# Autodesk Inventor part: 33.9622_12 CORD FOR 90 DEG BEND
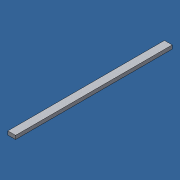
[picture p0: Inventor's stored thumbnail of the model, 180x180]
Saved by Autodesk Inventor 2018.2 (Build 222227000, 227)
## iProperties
Created: 2018-05
Part Number: 33.9622_12 CORD FOR 90 DEG BEND
Material: Generic
Document SubType Name: Modeling
Designer: amoles
Density: 1 g/cm^3
Appearance: White
Author: amoles
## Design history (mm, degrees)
sketch "Sketch1"
  geometry: L1 (-3.5, 1.65)-(3.5, 1.65); L2 (3.5, 1.65)-(3.5, -1.65); L3 (3.5, -1.65)-(-3.5, -1.65); L4 (-3.5, -1.65)-(-3.5, 1.65); 3 further points
  constraints: 8 end point, 2 midpoint, 2 parallel, 1 horizontal, 1 horizontal alignment, 1 perpendicular, 1 vertical alignment
  dimensions: "d0" = 7 distance of L1.start L1.end; "d1" = 3.3 distance of L1.end L2.end
extrude "Extrusion1" new body sketch "Sketch1" distance "d2" = 142.113; taper "d3" = 0 deg
body "Solid1"
